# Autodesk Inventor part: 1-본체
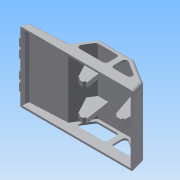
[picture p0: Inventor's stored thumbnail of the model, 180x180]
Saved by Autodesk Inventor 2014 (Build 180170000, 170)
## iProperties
Created: 2015-05
Part Number: 1-본체
Material: 알루미늄 6061
Document SubType Name: Modeling
Designer: Administrator
Density: 2.71 g/cm^3
Appearance: 알루미늄 - 평지
Mass: 105.21 g
Surface Area: 341.535 cm^2
Volume: 38.823 cm^3
Author: Administrator
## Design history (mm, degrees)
sketch "스케치1"
  geometry: L1 (0, 0)-(122, 0); L2 (54.409, 31)-(93, 31); L3 (1.144, 9)-(42, 11.141); L4 (42, 11.141)-(54.409, 31); L5 (122, 0)-(122, 1); L6 (122, 1)-(123, 1); L7 (123, 1)-(119.378, 14.517); L8 (93, 31)-(119.378, 14.517); L9 (119.378, 14.517)-(125.007, 11); L10 (0, 0)-(0, 1); L11 (0, 1)-(-1, 1); L12 (-1, 1)-(1.144, 9)
  constraints: 24 end point, 6 perpendicular, 1 horizontal, 1 parallel
  dimensions: "d0" = 122 distance of L1.start L1.end; "d46" = 42 horizontal distance of L3.end L1.start; "d47" = 125 deg angle of L4 L3; "d59" = 3 deg angle of L1 L3; "d63" = 31 vertical distance of L2.end L1.end; "d67" = 1 distance of L1.end L5.end; "d68" = 1 distance of L5.end L6.end; "d69" = 105 deg angle of L7 L1; "d70" = 30 horizontal distance of L6.end L2.end; "d73" = 20 vertical distance of L2.end L9.end; "d84" = 1 distance of L10.end L11.end; "d85" = 1 distance of L1.start L10.end; "d86" = 9 vertical distance of L3.start L1.start; "d87" = 105 deg angle of L1 L12
extrude "돌출1" new body sketch "스케치1" distance "d49" = 76; taper "d50" = 0 deg
feature "쉘1" dims "d83" = 2
sketch "스케치2"
  geometry: L1 (93, 31)-(54.409, 31) reference; L2 (54.409, 31)-(42, 11.141) reference; L3 (58.844, 26)-(78.808, 26); L4 (81.808, 23)-(81.808, 14); L5 (78.808, 11)-(53.22, 11); L6 (50.676, 15.59)-(56.299, 24.59); L7 (87.571, 23)-(87.571, 14); L8 (90.571, 11)-(105.109, 11); L9 (106.699, 16.544)-(91.566, 26); L10 (90.571, 26)-(91.566, 26); L11 (123, 1)-(119.378, 14.517) reference; L12 (119.378, 14.517)-(93, 31) reference; A1 r 3 centre (58.844, 23) between (58.844, 26) and (56.299, 24.59); A2 r 3 centre (53.22, 14) between (50.676, 15.59) and (53.22, 11); A3 r 3 centre (78.808, 14) between (78.808, 11) and (81.808, 14); A4 r 3 centre (78.808, 23) between (81.808, 23) and (78.808, 26); A5 r 3 centre (90.571, 23) between (90.571, 26) and (87.571, 23); A6 r 3 centre (105.109, 14) between (105.109, 11) and (106.699, 16.544); A7 r 3 centre (90.571, 14) between (87.571, 14) and (90.571, 11); 6 further points
  constraints: 16 end point, 14 point on circle, 14 tangent, 12 point on line, 7 centre point, 6 equal radius, 5 parallel, 3 perpendicular
  dimensions: "d52" = 5 distance between parallel lines of L1 L3; "d53" = 5 distance between parallel lines of L1 L10; "d54" = 28 distance of point (87.571, 11) point (115.571, 11); "d55" = 5 distance between parallel lines of L6 L2; "d56" = 34 distance of point (81.808, 11) point (47.808, 11); "d57" = 15 vertical distance of point (47.808, 11) point (57.181, 26); "d58" = 15 distance of point (87.571, 26) point (87.571, 11); "d74" = 5 distance between parallel lines of L12 L9; "d75" = 3 radius of A1
extrude "돌출2" cut sketch "스케치2" stored distance "d76" = 76; taper "d77" = 0 deg
node "작업 평면1"
sketch "스케치3"
  geometry: L1 (10.456, 51)-(30.456, 51); L2 (30.456, 51)-(30.456, 25); L3 (30.456, 25)-(10.456, 25); L4 (10.456, 25)-(10.456, 51); L5 (10.456, 51)-(30.456, 25); L6 (30.456, 51)-(10.456, 25); L7 (0, 76)-(0, 0) reference; L8 (40.912, 76)-(0, 76) reference; 6 further points
  constraints: 12 end point, 6 midpoint, 2 parallel, 1 horizontal, 1 horizontal alignment, 1 perpendicular, 1 vertical alignment
  dimensions: "d79" = 20 distance of L2.end L3.end; "d80" = 26 distance of L1.end L2.end
extrude "돌출3" join sketch "스케치3" stored distance "d81" = 76; taper "d82" = 0 deg
node "작업 평면2"
sketch "스케치4"
  geometry: L1 (0, 8.282)-(76, 8.282) reference; A1 r 4 centre (28, 0) between (32, 0) and (24, 0); A2 r 4 centre (48, 0) between (52, 0) and (44, 0); A3 r 4 centre (59, 0) between (63, 0) and (55, 0); A4 r 4 centre (17, 0) between (21, 0) and (13, 0); 4 further points
  constraints: 8 point on circle, 4 centre point, 3 equal radius, 14 other
  dimensions: "d89" = 4 radius of A4; "d90" = 11 distance of A1.centre A4.centre; "d91" = 11 distance of A3.centre A2.centre; "d92" = 20 distance of A2.centre A1.centre; "d93" = 10 distance of point (38, 0) A1.centre
extrude "돌출4" join sketch "스케치4" stored distance "d94" = 76; taper "d95" = 0 deg
sketch "스케치5"
  geometry: L1 (38.591, 0)-(38.591, -76) reference; L2 (68.591, 0)-(68.591, -76) reference; 3 further points
  constraints: 1 horizontal alignment, 1 midpoint, 1 other
  dimensions: "d96" = 50 horizontal distance of L2.start point (18.591, -38)
feature "엠보싱1" sketch "스케치5" dims "d97" = 0.5, "d98" = 0
node "작업 평면3"
sketch "스케치6"
  geometry: L1 (117.65, 13.239)-(92.427, 29) reference; L2 (92.427, 29)-(55.518, 29) reference; L3 (120.394, 3)-(117.65, 13.239) reference; L4 (0, 0)-(122, 0) reference; L5 (120, 0)-(120, 3) reference; L6 (120, 3)-(120.394, 3) reference; L7 (105.109, 11)-(90.571, 11) reference; L8 (91.566, 26)-(106.699, 16.544) reference; L9 (87.571, 14)-(87.571, 23) reference; L10 (92.427, 29)-(101.699, 2); L11 (101.699, 2)-(103.699, 2); L12 (111.969, 16.789)-(111.699, 2); L13 (111.699, 2)-(109.699, 2); L14 (103.699, 2)-(103.769, 0); L15 (109.699, 2)-(109.629, 0); L16 (106.699, 0)-(106.699, 16.544); L17 (92.427, 29)-(111.969, 16.789); A1 r 3 centre (105.109, 14) between (105.109, 11) and (106.699, 16.544) reference; A2 r 3 centre (90.571, 23) between (90.571, 26) and (87.571, 23) reference; A3 r 3 centre (90.571, 14) between (87.571, 14) and (90.571, 11) reference
  constraints: 16 end point, 4 point on line, 3 collinear, 2 perpendicular, 1 parallel
  dimensions: "d102" = 6 distance of L13.end L11.end; "d103" = 2 deg angle of L16 L14; "d105" = 2 deg angle of L16 L15; "d106" = 10 distance of L12.end L10.end; "d109" = 2 vertical distance of L15.end L12.end; "d110" = 20 deg angle of L12 L10; "d111" = 5 horizontal distance of L12.end L16.start
extrude "돌출5" join sketch "스케치6" stored distance "d112" = 10; taper "d113" = 0 deg
node "작업 평면4"
sketch "스케치7"
  geometry: L1 (92.427, 29)-(55.518, 29) reference; L2 (55.518, 29)-(43.144, 9.198) reference; L3 (0, 0)-(122, 0) reference; L4 (78.808, 11)-(53.22, 11) reference; L5 (50.676, 15.59)-(56.299, 24.59) reference; L6 (58.844, 26)-(78.808, 26) reference; L7 (81.808, 23)-(81.808, 14) reference; L8 (50.587, 21.109)-(61.014, 2); L9 (61.014, 2)-(62.922, 2); L10 (62.922, 2)-(64.014, 0); L11 (66.738, 29)-(70.831, 2); L12 (70.831, 2)-(68.922, 2); L13 (68.922, 2)-(67.831, 0); L14 (66.014, 11)-(66.014, 0); A1 r 3 centre (53.22, 14) between (50.676, 15.59) and (53.22, 11) reference; A2 r 3 centre (58.844, 23) between (58.844, 26) and (56.299, 24.59) reference; A3 r 3 centre (78.808, 23) between (81.808, 23) and (78.808, 26) reference; A4 r 3 centre (78.808, 14) between (78.808, 11) and (81.808, 14) reference
  constraints: 14 end point, 5 point on line, 2 equal length, 2 parallel, 1 collinear, 1 midpoint, 1 perpendicular
  dimensions: "d115" = 20 deg angle of L11 L8; "d116" = 2 distance from line of L3 L8.end; "d117" = 2 distance from line of L3 L11.end; "d118" = 5 horizontal distance of L14.end L8.end; "d119" = 28.6199 deg angle of L14 L10; "d120" = 6 distance of L12.end L9.end; "d121" = 2 distance of L14.end L10.end
extrude "돌출6" join sketch "스케치7" stored distance "d122" = 5; taper "d123" = 0 deg
node "작업 평면5"
node "작업 평면6"
fillet "모깎기1" dims "d144" = 3
fillet "모깎기2" dims "d145" = 3
fillet "모깎기3" dims "d146" = 3
fillet "모깎기4" dims "d147" = 3
node "솔리드1"
mirror "대칭1"
other parameters: "d78" = 5, "d88" = 2, "d114" = -21
